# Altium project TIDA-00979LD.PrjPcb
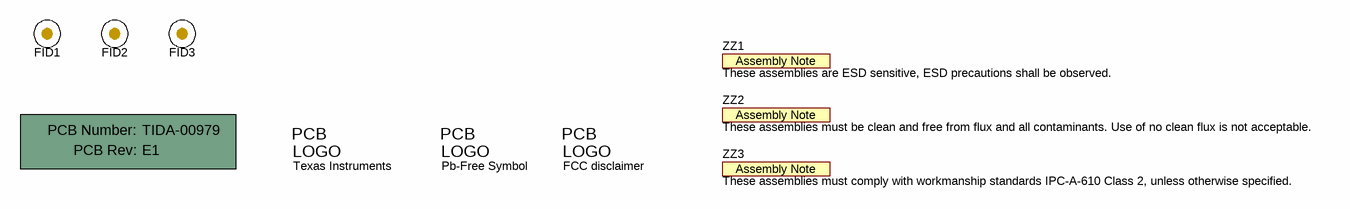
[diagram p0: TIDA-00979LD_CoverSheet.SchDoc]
CopyrightYear: 2016; PCB_Layout: GCD; PCB_Rev: E1; PRJ_Customer: Public Release; PRJ_Engineer: AW; PRJ_Number: TIDA-00979; PRJ_Title: Industrial Signal Light; SCH_Rev: E1; TechSupport: http://www.ti.com/support; TID: TIDA-00979LED
2 sheets, 32 parts. Net scope: flat (ports and power ports of the same name join across sheets).
Board file: TIDA-00979LD_PCB.PcbDoc
Sheets:
  TIDA-00979LD_CoverSheet.SchDoc
  TIDA-00979LD_LEDdriver.SchDoc

## Sheet TIDA-00979LD_CoverSheet.SchDoc: Block Diagram
size 431 x 279 mm; Date: Not shown in title block; ApprovedBy: Not shown in title block; CheckedBy: Not shown in title block; Author: Not shown in title block; CompanyName: Not shown in title block; DrawnBy: AW; Engineer: Not shown in title block; Organization: Not shown in title block; Address1: Not shown in title block; Address2: Not shown in title block; Address3: Not shown in title block; Address4: Not shown in title block; DocumentNumber: 1; Revision: Use project parameter SCH_Rev; SheetNumber: 1; SheetTotal: 2; PageSetup: Record=PageOptions¦CenterHorizontal=True¦CenterVertical=True¦PrintScale=1.00¦XCorrection=1.00¦YCorrection=1.00¦PrintKind=0¦BorderSize=5000000¦LeftOffset=0¦BottomOffset=0¦Orientation=2¦PaperLength=1000¦PaperWidth=1000¦Scale=100¦PaperSource=15¦PrintQuality=600¦MediaType=1¦DitherType=10¦PaperKind=Letter¦PrintScaleMode=1

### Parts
!PCB1  Printed Circuit Board  (value not drawn)  (mechanical)
FID1  Fiducial  [Fiducial10-20]  (value not drawn)
FID2  Fiducial  [Fiducial10-20]  (value not drawn)
FID3  Fiducial  [Fiducial10-20]  (value not drawn)
Logo1  Texas Instruments  [TI_Symbol_Overlay_Small]  (no BOM)
Logo2  Pb-Free Symbol  [Pb-Free_Overlay_Small]  (no BOM)
Logo3  FCC disclaimer  [FCC_disclaimer_stacked]  (no BOM)
ZZ1  These assemblies are ESD sensitive, ESD precautions shall be observed.  [AssemblyNote]  (no BOM)
ZZ2  These assemblies must be clean and free from flux and all contaminants. Use of no clean flux is not acceptable.  [AssemblyNote]  (no BOM)
ZZ3  These assemblies must comply with workmanship standards IPC-A-610 Class 2, unless otherwise specified.  [AssemblyNote]  (no BOM)

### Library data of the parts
!PCB1 = PCB: Manufacturer: Any; PartNumber: TIDA-00979; SymbolCreator: a0412235
FID1-FID3 = Fiducial: Fiducial mark.  There is nothing to buy or mount.; SymbolCreator: codlsc
Logo1 = TI_Logo: Texas Instrument Corporate Signature; SymbolCreator: codlsc
Logo2 = Pb-Free: SymbolCreator: a0412235
Logo3 = FCC_disclaimer: SymbolCreator: codlsc
ZZ1-ZZ3 = AssemblyNote: SymbolCreator: codlsc

## Sheet TIDA-00979LD_LEDdriver.SchDoc: LED Panel
size 431 x 279 mm; Date: Not shown in title block; ApprovedBy: Not shown in title block; CheckedBy: Not shown in title block; Author: Not shown in title block; CompanyName: Not shown in title block; DrawnBy: AW; Engineer: Not shown in title block; Organization: Not shown in title block; Address1: Not shown in title block; Address2: Not shown in title block; Address3: Not shown in title block; Address4: Not shown in title block; DocumentNumber: 2; Revision: Use project parameter SCH_Rev; SheetNumber: 2; SheetTotal: 2; PageSetup: Record=PageOptions¦CenterHorizontal=True¦CenterVertical=True¦PrintScale=1.00¦XCorrection=1.00¦YCorrection=1.00¦PrintKind=0¦BorderSize=5000000¦LeftOffset=0¦BottomOffset=0¦Orientation=2¦PaperLength=1000¦PaperWidth=1000¦Scale=100¦PaperSource=15¦PrintQuality=600¦MediaType=1¦DitherType=10¦PaperKind=Letter¦PrintScaleMode=1
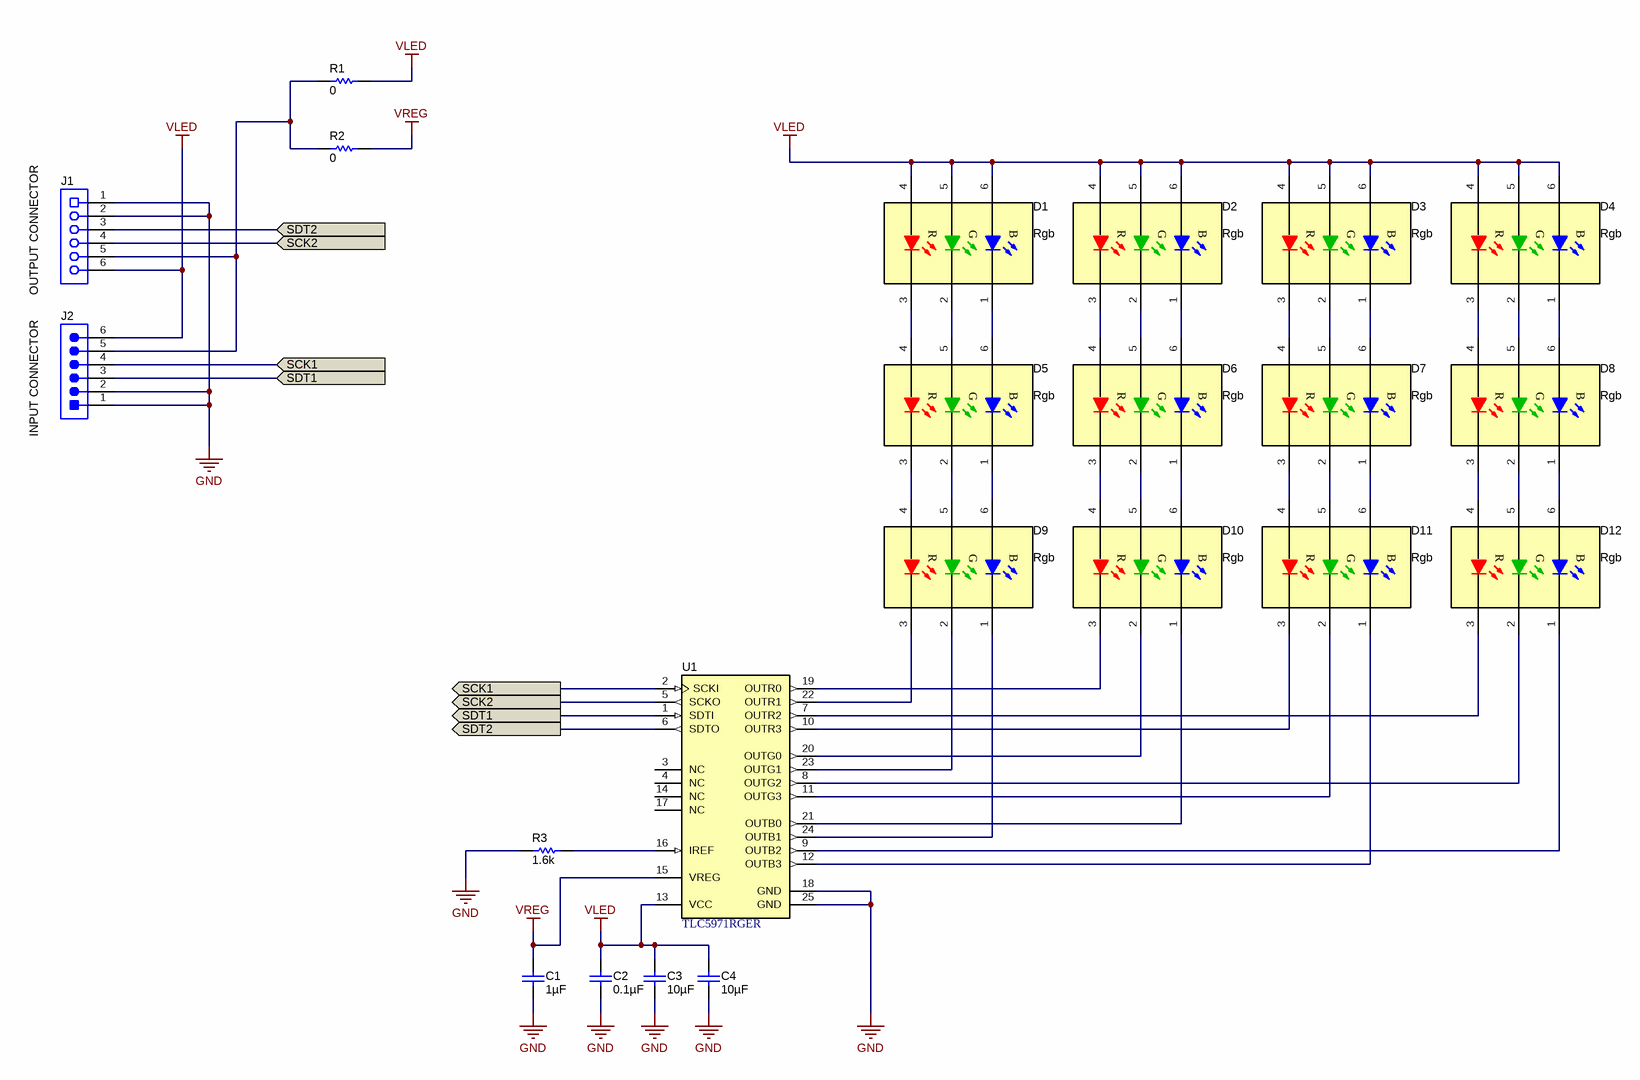
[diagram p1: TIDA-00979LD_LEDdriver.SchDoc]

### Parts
C1  ValueDisplayed: 1µF  [0402]  (hidden comment: GRM155R70J105MA12D)
C2  ValueDisplayed: 0.1µF  [0402]  (hidden comment: GRM155R71E104KE14D)
C3  ValueDisplayed: 10µF  [0603]  (hidden comment: C1608X5R1E106M080AC)
C4  ValueDisplayed: 10µF  [0603]  (hidden comment: C1608X5R1E106M080AC)
D1  value Rgb  [CLX6C-FKB_RGB]  (hidden comment: CLX6C-FKB-CGJKNCFBB789363)
D2  value Rgb  [CLX6C-FKB_RGB]  (hidden comment: CLX6C-FKB-CGJKNCFBB789363)
D3  value Rgb  [CLX6C-FKB_RGB]  (hidden comment: CLX6C-FKB-CGJKNCFBB789363)
D4  value Rgb  [CLX6C-FKB_RGB]  (hidden comment: CLX6C-FKB-CGJKNCFBB789363)
D5  value Rgb  [CLX6C-FKB_RGB]  (hidden comment: CLX6C-FKB-CGJKNCFBB789363)
D6  value Rgb  [CLX6C-FKB_RGB]  (hidden comment: CLX6C-FKB-CGJKNCFBB789363)
D7  value Rgb  [CLX6C-FKB_RGB]  (hidden comment: CLX6C-FKB-CGJKNCFBB789363)
D8  value Rgb  [CLX6C-FKB_RGB]  (hidden comment: CLX6C-FKB-CGJKNCFBB789363)
D9  value Rgb  [CLX6C-FKB_RGB]  (hidden comment: CLX6C-FKB-CGJKNCFBB789363)
D10  value Rgb  [CLX6C-FKB_RGB]  (hidden comment: CLX6C-FKB-CGJKNCFBB789363)
D11  value Rgb  [CLX6C-FKB_RGB]  (hidden comment: CLX6C-FKB-CGJKNCFBB789363)
D12  value Rgb  [CLX6C-FKB_RGB]  (hidden comment: CLX6C-FKB-CGJKNCFBB789363)
J1  851-11-006-40-001000  [Mill-Max_851-11-006-40-001000]  (value not drawn)
J2  850-10-006-40-001000  [Mill-Max_850-10-006-40-001000]  (value not drawn)
R1  ValueDisplayed: 0  [0603]  (hidden comment: CRCW06030000Z0EA)
R2  ValueDisplayed: 0  [0603]  (hidden comment: CRCW06030000Z0EA)
R3  ValueDisplayed: 1.6k  [0402]  (hidden comment: CRCW04021K60JNED)
U1  TLC5971RGER  [RGE0024H]

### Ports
SCK1, SCK2, SDT1, SDT2

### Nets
GND: C1.2 C2.2 C3.2 C4.2 J1.1 J1.2 J2.1 J2.2 R3.2 U1.18(GND) U1.25(GND)
VLED: C2.1 C3.1 C4.1 D1.4(A) D1.5(A) D1.6(A) D2.4(A) D2.5(A) D2.6(A) D3.4(A) D3.5(A) D3.6(A) D4.4(A) D4.5(A) D4.6(A) J1.6 J2.6 R1.2 U1.13(VCC)
VREG: C1.1 R2.2 U1.15(VREG)
SCK1: J2.4 U1.2(SCKI) ; port SCK1
SCK2: J1.4 U1.5(SCKO) ; port SCK2
SDT1: J2.3 U1.1(SDTI) ; port SDT1
SDT2: J1.3 U1.6(SDTO) ; port SDT2
NetD1_1: D1.1(K) D5.6(A)
NetD1_2: D1.2(K) D5.5(A)
NetD1_3: D1.3(K) D5.4(A)
NetD2_1: D2.1(K) D6.6(A)
NetD2_2: D2.2(K) D6.5(A)
NetD2_3: D2.3(K) D6.4(A)
NetD3_1: D3.1(K) D7.6(A)
NetD3_2: D3.2(K) D7.5(A)
NetD3_3: D3.3(K) D7.4(A)
NetD4_1: D4.1(K) D8.6(A)
NetD4_2: D4.2(K) D8.5(A)
NetD4_3: D4.3(K) D8.4(A)
NetD5_1: D5.1(K) D9.6(A)
NetD5_2: D5.2(K) D9.5(A)
NetD5_3: D5.3(K) D9.4(A)
NetD6_1: D6.1(K) D10.6(A)
NetD6_2: D6.2(K) D10.5(A)
NetD6_3: D6.3(K) D10.4(A)
NetD7_1: D7.1(K) D11.6(A)
NetD7_2: D7.2(K) D11.5(A)
NetD7_3: D7.3(K) D11.4(A)
NetD8_1: D8.1(K) D12.6(A)
NetD8_2: D8.2(K) D12.5(A)
NetD8_3: D8.3(K) D12.4(A)
NetD9_1: D9.1(K) U1.24(OUTB1)
NetD9_2: D9.2(K) U1.23(OUTG1)
NetD9_3: D9.3(K) U1.22(OUTR1)
NetD10_1: D10.1(K) U1.21(OUTB0)
NetD10_2: D10.2(K) U1.20(OUTG0)
NetD10_3: D10.3(K) U1.19(OUTR0)
NetD11_1: D11.1(K) U1.12(OUTB3)
NetD11_2: D11.2(K) U1.11(OUTG3)
NetD11_3: D11.3(K) U1.10(OUTR3)
NetD12_1: D12.1(K) U1.9(OUTB2)
NetD12_2: D12.2(K) U1.8(OUTG2)
NetD12_3: D12.3(K) U1.7(OUTR2)
NetJ1_5: J1.5 J2.5 R1.1 R2.1
NetR3_1: R3.1 U1.16(IREF)

Not connected (* = marked no-connect by the designer): U1 3(NC) 4(NC) 14(NC) 17(NC)

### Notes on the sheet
- (near J1) OUTPUT CONNECTOR
- (near J2) INPUT CONNECTOR

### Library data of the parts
C1 = GRM155R70J105MA12D: CAP, CERM, 1 µF, 6.3 V, +/- 20%, X7R, 0402; Manufacturer: MuRata; Polarized: N; CompType: Capacitor; Value: 1uF; U/M: EA; Cap_F: 0.000001; Tolerance_%: 20; Value1: Unknown; VDC_V: 6.3; Value2: 6.3V; TaMin_C: -55; TaMax_C: 125; AEC Category: Q200
C2 = GRM155R71E104KE14D: CAP, CERM, 0.1 µF, 25 V, +/- 10%, X7R, 0402; Manufacturer: MuRata; Polarized: N; CompType: Capacitor; Value: 0.1uF; U/M: EA; Cap_F: 0.0000001; Tolerance_%: 10; Value1: Unknown; VDC_V: 25; Value2: 25V; TaMin_C: -55; TaMax_C: 125; AEC Category: Q200
C3 C4 = C1608X5R1E106M080AC: CAP, CERM, 10 µF, 25 V, +/- 20%, X5R, 0603; Manufacturer: TDK; Polarized: N; CompType: Capacitor; Value: 10uF; U/M: EA; Cap_F: 0.00001; Tolerance_%: 20; Value1: Unknown; VDC_V: 25; Value2: 25V; TaMin_C: -55; TaMax_C: 85; AEC Category: Q200
D1-D12 = CLX6C-FKB-CGJKNCFBB789363: LED, Rgb, SMD; Manufacturer: Cree; SymbolCreator: Altium; Vf_V: 3; Value2: 3V; Io_A: 0.02; Vr_V: 5; Ir_A: 1e-005; Tjmax_C: 110; Value1: W; U/M: EA
J1 = 851-11-006-40-001000: Receptacle, 50mil, 5x1, Gold, R/A, SMT; Manufacturer: Mill-Max; SymbolCreator: a0411947; Gender: Female; Row_Count: 1; Current_A: 3
J2 = 850-10-006-40-001000: Header, 50mil, 6x1, Gold, R/A, SMT; Manufacturer: Mill-Max; SymbolCreator: a0412235; Gender: Male; Row_Count: 1; Current_A: 3
R1 R2 = CRCW06030000Z0EA: RES, 0, 5%, 0.1 W, 0603; Manufacturer: Vishay-Dale; CompType: Resistor; Value: 0; Value_Code: 0000; Tolerance_%: 5; Power_W: 0.1; Value2: 0.1W; VDC_V: 75; TempCo: 200 ppm/C; EIA_Code: E24; U/M: EA; AEC Category: Q200
R3 = CRCW04021K60JNED: RES, 1.6 k, 5%, 0.063 W, 0402; Manufacturer: Vishay-Dale; CompType: Resistor; Value: 1.6k; Res_ohm: 1600; Value_Code: 1k60; Tolerance_%: 5; Power_W: 0.063; Value2: 0.063W; VDC_V: 50; TempCo: 200 ppm/C; EIA_Code: E24; U/M: EA; AEC Category: Q200
U1 = TLC5971RGER: 12-Channel, 16-Bit ES-PWM RGB LED Driver with 3.3 V Linear Regulator, 6 to 17 V, -40 to 85 degC, 24-pin QFN (RGE24), Green (RoHS & no Sb/Br); Manufacturer: Texas Instruments; Alternate PartNumber: Equivalent; Rating: Catalog; Vin(Max)(V): 17; Vin(Min)(V): 6

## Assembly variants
TID: not fitted FID1 FID1 FID2 FID2 FID3 FID3 R2
EVM: not fitted FID1 FID2 FID3 R2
